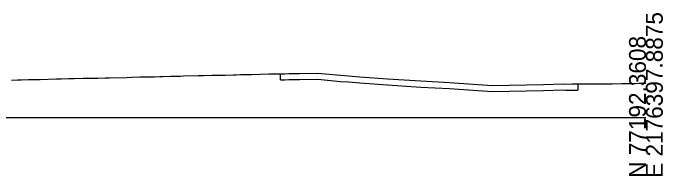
# Model space of a CAD drawing. Extents: x 2199216 to 2207488, y 61398 to 70914.
# Drawn here: x 2206128.4 to 2206236.3, y 67397.6 to 67424.6 of the extents above; entities that cross this region are included whole.
import ezdxf

# ---------------------------------------------------------------- set-up
doc = ezdxf.new("R2010")
doc.units = 0
for name, color, linetype in [('Exist Cross Section Cell', 7, 'Continuous'), ('Exist PHM Roadway Shape', 7, 'Continuous'), ('Exist XS Ground Line', 7, 'Continuous')]:
    doc.layers.add(name, color=color, linetype=linetype)

msp = doc.modelspace()

# ---------------------------------------------------------------- linework, layer by layer
at = {"layer": 'Exist Cross Section Cell'}
msp.add_line((2206033.5, 67407.31), (2206233.5, 67407.31), dxfattribs=at)
at = {"layer": 'Exist PHM Roadway Shape'}
for p, q in [((2206172.8, 67413.57), (2206172.8, 67414.57)), ((2206172.8, 67413.57), (2206173.53, 67413.58)), ((2206172.8, 67413.57), (2206172.8, 67413.57)), ((2206173.53, 67413.58), (2206174.18, 67413.6)), ((2206174.18, 67413.6), (2206175.57, 67413.61)), ((2206175.57, 67413.61), (2206176, 67413.62)), ((2206176, 67413.62), (2206179.03, 67413.65)), ((2206179.03, 67413.65), (2206182.76, 67413.31)), ((2206182.76, 67413.31), (2206184.13, 67413.2)), ((2206184.13, 67413.2), (2206186.01, 67413.05)), ((2206186.01, 67413.05), (2206190.61, 67412.75)), ((2206190.61, 67412.75), (2206196.12, 67412.37)), ((2206196.12, 67412.37), (2206200.89, 67412.1)), ((2206200.89, 67412.1), (2206207.95, 67411.6)), ((2206207.95, 67411.6), (2206216.5, 67411.81)), ((2206216.5, 67411.81), (2206219.75, 67411.88)), ((2206219.75, 67411.88), (2206220.22, 67411.86)), ((2206220.22, 67411.86), (2206221.26, 67411.87)), ((2206221.26, 67411.87), (2206222.2, 67411.87)), ((2206222.2, 67412.87), (2206222.2, 67411.87)), ((2206222.2, 67411.87), (2206222.2, 67411.87))]:
    msp.add_line(p, q, dxfattribs=at)
at = {"layer": 'Exist XS Ground Line'}
msp.add_lwpolyline([(2206128.14, 67413.51), (2206129.17, 67413.54), (2206129.79, 67413.56), (2206130.99, 67413.59), (2206132.93, 67413.64), (2206135.62, 67413.71), (2206136.42, 67413.73), (2206137.7, 67413.76), (2206138.23, 67413.77), (2206138.56, 67413.78), (2206140.05, 67413.81), (2206141.5, 67413.84), (2206141.87, 67413.85), (2206142.47, 67413.86), (2206143.69, 67413.89), (2206144.43, 67413.91), (2206147.29, 67413.97), (2206148.12, 67414), (2206149.46, 67414.04), (2206151.51, 67414.07), (2206151.97, 67414.08), (2206152.76, 67414.1), (2206153.24, 67414.11), (2206154.57, 67414.15), (2206156.19, 67414.19), (2206156.71, 67414.2), (2206159.14, 67414.26), (2206160.02, 67414.28), (2206161.44, 67414.32), (2206162.09, 67414.33), (2206163.65, 67414.36), (2206165.04, 67414.4), (2206165.47, 67414.41), (2206166.16, 67414.42), (2206167.28, 67414.45), (2206167.98, 67414.47), (2206170.87, 67414.53), (2206172.11, 67414.56), (2206172.8, 67414.57), (2206173.53, 67414.58), (2206174.18, 67414.6), (2206175.57, 67414.61), (2206176, 67414.62), (2206179.03, 67414.65), (2206182.76, 67414.31), (2206184.13, 67414.2), (2206186.01, 67414.05), (2206190.61, 67413.75), (2206196.12, 67413.37), (2206200.89, 67413.1), (2206207.95, 67412.6), (2206216.5, 67412.81), (2206219.75, 67412.88), (2206220.22, 67412.86), (2206221.26, 67412.87), (2206222.2, 67412.87), (2206224.51, 67412.88), (2206225.37, 67412.89), (2206226.69, 67412.9), (2206227.36, 67412.91), (2206227.93, 67412.91), (2206229.51, 67412.93), (2206231.69, 67412.97), (2206232.34, 67412.98), (2206233.5, 67413)], dxfattribs=at)

# ---------------------------------------------------------------- texts
at = {"layer": 'Exist Cross Section Cell'}
for s, p in [('E 2176397.8875', (2206236.3, 67397.31)), ('N 77192.3608', (2206233.5, 67397.31))]:
    msp.add_text(s, height=2.8, rotation=90, dxfattribs=at).set_placement(p)

doc.saveas('drawing.dxf')
